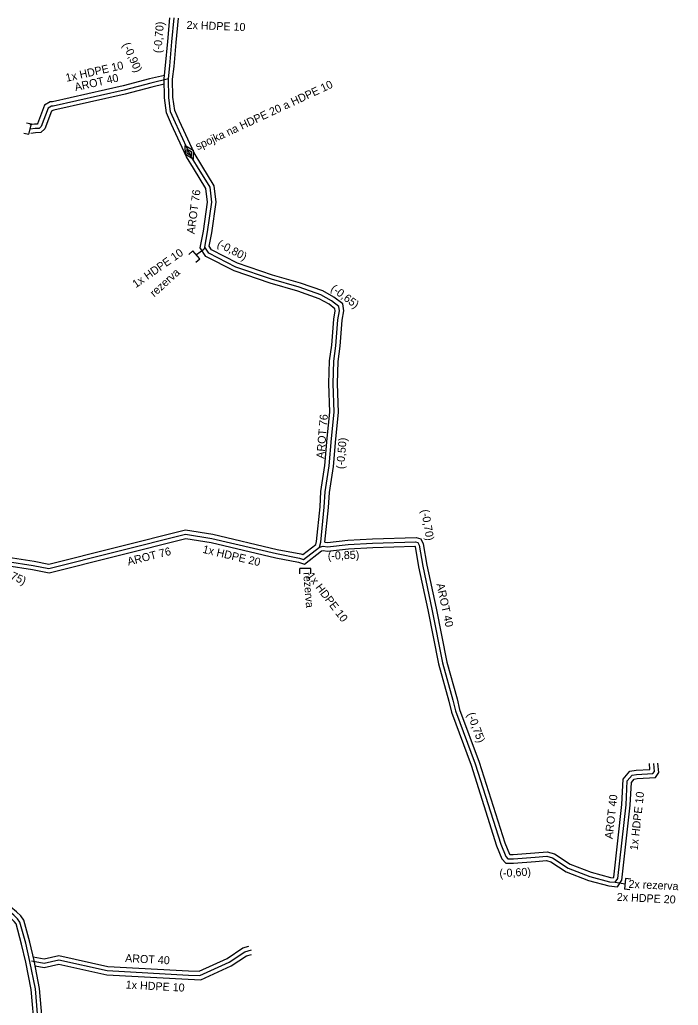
# Model space of a CAD drawing. Extents: x -651943 to -618711, y -1138561 to -1100552.
# Drawn here: x -634858.3 to -634796.6, y -1115408.5 to -1115316.1 of the extents above; entities that cross this region are included whole.
import ezdxf

# ---------------------------------------------------------------- set-up
doc = ezdxf.new("R2010")
doc.units = 0
for name, color, linetype in [('KT optika', 7, 'Continuous'), ('KT trasa', 7, 'Continuous'), ('KT zařízení', 7, 'Continuous')]:
    doc.layers.add(name, color=color, linetype=linetype)

# ---------------------------------------------------------------- blocks, each defined once
blk = doc.blocks.new('TVSPO_1')
at = {"layer": 'KT zařízení'}
for p, q in [((-0.074, 0.0016), (-0.0005, 0.0439)), ((-0.0005, -0.0409), (-0.074, 0.0016)), ((-0.0353, -0.0001), (0, 0.0203)), ((-0.0005, 0.0439), (0.0728, 0.0015)), ((0.0728, 0.0015), (-0.0005, -0.0409)), ((0, 0.0203), (0.0353, 0.0001)), ((0.0353, 0.0001), (0, -0.0204)), ((0, -0.0204), (-0.0353, -0.0001))]:
    blk.add_line(p, q, dxfattribs=at)
blk = doc.blocks.new('TVREZ')
at = {"layer": 'KT zařízení'}
for p, q in [((-0.05, 0.05), (0, 0.05)), ((0, -0.05), (0, 0.05)), ((-0.05, -0.05), (0, -0.05))]:
    blk.add_line(p, q, dxfattribs=at)

msp = doc.modelspace()

# ---------------------------------------------------------------- linework, layer by layer
at = {"layer": 'KT optika'}
for p, q in [((-634842.79, -1115364.35), (-634840.32, -1115364.75)), ((-634802.52, -1115396.99), (-634801.606, -1115397.145))]:
    msp.add_line(p, q, dxfattribs=at)
for points in [[(-634841.66, -1115329.93), (-634842.35, -1115328.79), (-634843.74, -1115325.8), (-634844.19, -1115324.75), (-634844.37, -1115323.43), (-634844.4, -1115321.67), (-634844.27, -1115320.46), (-634844.07, -1115318.21), (-634843.85, -1115315.96)], [(-634844.4, -1115321.67), (-634846.06, -1115322.06), (-634848.54, -1115322.72), (-634855.19, -1115324.22), (-634855.36, -1115324.23), (-634855.68, -1115324.42), (-634856.32, -1115326.13), (-634856.52, -1115326.31), (-634856.9, -1115326.32), (-634857.342, -1115326.385)], [(-634840.34, -1115333.24), (-634840.5, -1115331.83), (-634841.66, -1115329.93)], [(-634830.24, -1115365.56), (-634830.13, -1115365.11), (-634829.79, -1115361.83), (-634829.71, -1115360.39), (-634829.33, -1115357.96), (-634829.11, -1115355.38), (-634828.87, -1115352.93), (-634828.95, -1115350.24), (-634828.89, -1115348.14), (-634828.7, -1115346.69), (-634828.51, -1115344.25), (-634828.354, -1115343.417), (-634828.422, -1115342.998), (-634829.126, -1115342.471), (-634830.101, -1115341.917), (-634832.145, -1115341.2), (-634834.75, -1115340.445), (-634838.094, -1115339.309), (-634840.626, -1115338.011), (-634840.992, -1115337.444), (-634840.721, -1115336.024), (-634840.34, -1115333.24)], [(-634840.992, -1115337.444), (-634841.08, -1115337.67), (-634841.78, -1115338.16)], [(-634857.06, -1115367.28), (-634855.6, -1115367.56), (-634842.79, -1115364.35), (-634840.32, -1115364.75), (-634834.27, -1115366.18)], [(-634866.13, -1115365.07), (-634864.21, -1115365.83), (-634862.51, -1115366.54), (-634861.65, -1115366.57), (-634859.49, -1115366.91), (-634857.06, -1115367.28)], [(-634834.27, -1115366.18), (-634832.1, -1115366.6), (-634831.73, -1115366.72), (-634830.24, -1115365.56), (-634829.91, -1115365.47), (-634829.49, -1115365.54), (-634827.55, -1115365.33), (-634825.26, -1115365.19), (-634821.24, -1115365.06), (-634821.03, -1115365.13), (-634820.9, -1115365.39), (-634820.57, -1115367.34), (-634819.7, -1115371.37), (-634818.71, -1115376.43), (-634817.74, -1115379.9), (-634817.49, -1115380.92), (-634815.64, -1115385.87), (-634813.26, -1115393.42), (-634812.79, -1115394.57), (-634812.6, -1115394.8), (-634812.07, -1115394.79), (-634810.02, -1115394.63), (-634808.939, -1115394.544), (-634808.397, -1115394.688), (-634806.94, -1115395.66), (-634804.91, -1115396.43), (-634803.05, -1115396.94), (-634802.52, -1115396.99), (-634802.28, -1115396.64), (-634801.51, -1115389.74), (-634801.4, -1115387.48), (-634800.95, -1115386.95), (-634800.52, -1115386.87), (-634798.99, -1115386.79), (-634798.86, -1115386.59), (-634798.917, -1115385.837)], [(-634857.756, -1115443.558), (-634856.196, -1115437.459), (-634855.073, -1115432.467), (-634854.315, -1115428.401), (-634854.12, -1115426.649), (-634854.295, -1115424.564), (-634854.363, -1115424.131), (-634854.471, -1115423.78), (-634854.74, -1115423.07), (-634855.771, -1115420.67), (-634856.123, -1115416.425), (-634856.529, -1115410.896), (-634856.867, -1115406.99), (-634857.381, -1115404.408), (-634857.768, -1115402.684), (-634858.309, -1115400.724), (-634858.539, -1115400.4), (-634858.891, -1115400.062), (-634859.92, -1115399.223), (-634862.06, -1115398.101), (-634864.36, -1115396.34), (-634866.769, -1115395.591)], [(-634857.24, -1115404.36), (-634856.04, -1115404.56), (-634854.68, -1115404.25), (-634850.13, -1115405.27), (-634842.53, -1115405.68), (-634841.45, -1115405.74), (-634838.7, -1115404.48), (-634837.25, -1115403.51), (-634836.609, -1115403.321)]]:
    msp.add_lwpolyline(points, dxfattribs=at)
at = {"layer": 'KT trasa'}
for p, q in [((-634842.79, -1115364.35), (-634840.32, -1115364.75)), ((-634802.52, -1115396.99), (-634801.606, -1115397.145))]:
    msp.add_line(p, q, dxfattribs=at)
for points in [[(-634841.66, -1115329.93), (-634842.35, -1115328.79), (-634843.74, -1115325.8), (-634844.19, -1115324.75), (-634844.37, -1115323.43), (-634844.4, -1115321.67), (-634844.27, -1115320.46), (-634844.07, -1115318.21), (-634843.85, -1115315.96)], [(-634844.4, -1115321.67), (-634846.06, -1115322.06), (-634848.54, -1115322.72), (-634855.19, -1115324.22), (-634855.36, -1115324.23), (-634855.68, -1115324.42), (-634856.32, -1115326.13), (-634856.52, -1115326.31), (-634856.9, -1115326.32), (-634857.342, -1115326.385)], [(-634840.34, -1115333.24), (-634840.5, -1115331.83), (-634841.66, -1115329.93)], [(-634830.24, -1115365.56), (-634830.13, -1115365.11), (-634829.79, -1115361.83), (-634829.71, -1115360.39), (-634829.33, -1115357.96), (-634829.11, -1115355.38), (-634828.87, -1115352.93), (-634828.95, -1115350.24), (-634828.89, -1115348.14), (-634828.7, -1115346.69), (-634828.51, -1115344.25), (-634828.354, -1115343.417), (-634828.422, -1115342.998), (-634829.126, -1115342.471), (-634830.101, -1115341.917), (-634832.145, -1115341.2), (-634834.75, -1115340.445), (-634838.094, -1115339.309), (-634840.626, -1115338.011), (-634840.992, -1115337.444), (-634840.721, -1115336.024), (-634840.34, -1115333.24)], [(-634840.992, -1115337.444), (-634841.08, -1115337.67), (-634841.78, -1115338.16)], [(-634857.06, -1115367.28), (-634855.6, -1115367.56), (-634842.79, -1115364.35), (-634840.32, -1115364.75), (-634834.27, -1115366.18)], [(-634866.13, -1115365.07), (-634864.21, -1115365.83), (-634862.51, -1115366.54), (-634861.65, -1115366.57), (-634859.49, -1115366.91), (-634857.06, -1115367.28)], [(-634834.27, -1115366.18), (-634832.1, -1115366.6), (-634831.73, -1115366.72), (-634830.24, -1115365.56), (-634829.91, -1115365.47), (-634829.49, -1115365.54), (-634827.55, -1115365.33), (-634825.26, -1115365.19), (-634821.24, -1115365.06), (-634821.03, -1115365.13), (-634820.9, -1115365.39), (-634820.57, -1115367.34), (-634819.7, -1115371.37), (-634818.71, -1115376.43), (-634817.74, -1115379.9), (-634817.49, -1115380.92), (-634815.64, -1115385.87), (-634813.26, -1115393.42), (-634812.79, -1115394.57), (-634812.6, -1115394.8), (-634812.07, -1115394.79), (-634810.02, -1115394.63), (-634808.939, -1115394.544), (-634808.397, -1115394.688), (-634806.94, -1115395.66), (-634804.91, -1115396.43), (-634803.05, -1115396.94), (-634802.52, -1115396.99), (-634802.28, -1115396.64), (-634801.51, -1115389.74), (-634801.4, -1115387.48), (-634800.95, -1115386.95), (-634800.52, -1115386.87), (-634798.99, -1115386.79), (-634798.86, -1115386.59), (-634798.917, -1115385.837)], [(-634857.756, -1115443.558), (-634856.196, -1115437.459), (-634855.073, -1115432.467), (-634854.315, -1115428.401), (-634854.12, -1115426.649), (-634854.295, -1115424.564), (-634854.363, -1115424.131), (-634854.471, -1115423.78), (-634854.74, -1115423.07), (-634855.771, -1115420.67), (-634856.123, -1115416.425), (-634856.529, -1115410.896), (-634856.867, -1115406.99), (-634857.381, -1115404.408), (-634857.768, -1115402.684), (-634858.309, -1115400.724), (-634858.539, -1115400.4), (-634858.891, -1115400.062), (-634859.92, -1115399.223), (-634862.06, -1115398.101), (-634864.36, -1115396.34), (-634866.769, -1115395.591)], [(-634857.24, -1115404.36), (-634856.04, -1115404.56), (-634854.68, -1115404.25), (-634850.13, -1115405.27), (-634842.53, -1115405.68), (-634841.45, -1115405.74), (-634838.7, -1115404.48), (-634837.25, -1115403.51), (-634836.609, -1115403.321)]]:
    msp.add_lwpolyline(points, dxfattribs=at)
at = {"layer": 'KT zařízení'}
for points in [[(-634842.052, -1115330.054), (-634842.704, -1115328.978), (-634844.105, -1115325.963), (-634844.579, -1115324.858), (-634844.77, -1115323.461), (-634844.8, -1115321.652), (-634844.668, -1115320.421), (-634844.468, -1115318.173), (-634844.25, -1115315.936)], [(-634841.278, -1115329.79), (-634841.996, -1115328.602), (-634843.375, -1115325.637), (-634843.801, -1115324.642), (-634843.97, -1115323.399), (-634844, -1115321.688), (-634843.872, -1115320.499), (-634843.672, -1115318.247), (-634843.45, -1115315.984)], [(-634844.767, -1115321.346), (-634846.157, -1115321.672), (-634848.635, -1115322.331), (-634855.246, -1115323.823), (-634855.481, -1115323.836), (-634856.005, -1115324.148), (-634856.66, -1115325.898), (-634856.678, -1115325.914), (-634856.934, -1115325.921), (-634857.4, -1115325.989)], [(-634844.791, -1115322.172), (-634845.963, -1115322.448), (-634848.445, -1115323.109), (-634855.134, -1115324.617), (-634855.239, -1115324.624), (-634855.355, -1115324.692), (-634855.98, -1115326.362), (-634856.362, -1115326.706), (-634856.866, -1115326.719), (-634857.284, -1115326.781)], [(-634840.743, -1115333.235), (-634840.887, -1115331.963), (-634842.052, -1115330.054)], [(-634839.937, -1115333.245), (-634840.113, -1115331.697), (-634841.278, -1115329.79)], [(-634830.596, -1115365.33), (-634830.525, -1115365.042), (-634830.189, -1115361.798), (-634830.108, -1115360.348), (-634829.727, -1115357.912), (-634829.508, -1115355.344), (-634829.271, -1115352.916), (-634829.35, -1115350.24), (-634829.289, -1115348.108), (-634829.098, -1115346.648), (-634828.907, -1115344.198), (-634828.76, -1115343.412), (-634828.791, -1115343.221), (-634829.346, -1115342.806), (-634830.267, -1115342.283), (-634832.267, -1115341.581), (-634834.87, -1115340.827), (-634838.25, -1115339.678), (-634840.904, -1115338.318), (-634841.415, -1115337.526), (-634841.116, -1115335.959), (-634840.743, -1115333.235)], [(-634829.726, -1115365.095), (-634829.391, -1115361.862), (-634829.312, -1115360.432), (-634828.933, -1115358.008), (-634828.712, -1115355.416), (-634828.469, -1115352.944), (-634828.55, -1115350.24), (-634828.491, -1115348.172), (-634828.302, -1115346.732), (-634828.113, -1115344.302), (-634827.948, -1115343.422), (-634828.053, -1115342.775), (-634828.906, -1115342.136), (-634829.935, -1115341.551), (-634832.023, -1115340.819), (-634834.63, -1115340.063), (-634837.938, -1115338.94), (-634840.348, -1115337.704), (-634840.569, -1115337.362), (-634840.326, -1115336.089), (-634839.937, -1115333.245)], [(-634856.978, -1115366.888), (-634855.611, -1115367.151), (-634842.807, -1115363.942), (-634840.242, -1115364.357), (-634834.199, -1115365.786)], [(-634865.996, -1115364.693), (-634864.059, -1115365.459), (-634862.423, -1115366.143), (-634861.612, -1115366.171), (-634859.429, -1115366.515), (-634856.978, -1115366.888)], [(-634857.142, -1115367.672), (-634855.589, -1115367.969), (-634842.773, -1115364.758), (-634840.398, -1115365.143), (-634834.341, -1115366.574)], [(-634834.199, -1115365.786), (-634832, -1115366.212), (-634831.808, -1115366.274), (-634830.596, -1115365.33)], [(-634829.726, -1115365.095), (-634829.478, -1115365.136), (-634827.584, -1115364.931), (-634825.279, -1115364.79), (-634821.181, -1115364.658), (-634820.746, -1115364.803), (-634820.516, -1115365.264), (-634820.177, -1115367.264), (-634819.308, -1115371.289), (-634818.32, -1115376.338), (-634817.353, -1115379.799), (-634817.107, -1115380.802), (-634815.262, -1115385.74), (-634812.883, -1115393.284), (-634812.443, -1115394.362), (-634812.415, -1115394.396), (-634812.089, -1115394.39), (-634810.051, -1115394.231), (-634808.902, -1115394.14), (-634808.23, -1115394.318), (-634806.756, -1115395.302), (-634804.786, -1115396.049), (-634802.978, -1115396.545), (-634802.717, -1115396.57), (-634802.666, -1115396.496), (-634801.909, -1115389.708), (-634801.793, -1115387.325), (-634801.163, -1115386.583), (-634800.567, -1115386.472), (-634799.275, -1115386.404), (-634799.316, -1115385.867)], [(-634866.264, -1115365.447), (-634864.361, -1115366.201), (-634862.597, -1115366.937), (-634861.688, -1115366.969), (-634859.551, -1115367.305), (-634857.142, -1115367.672)], [(-634834.341, -1115366.574), (-634832.2, -1115366.988), (-634831.652, -1115367.166), (-634830.057, -1115365.925), (-634829.889, -1115365.879), (-634829.502, -1115365.944), (-634827.516, -1115365.729), (-634825.241, -1115365.59), (-634821.311, -1115365.463), (-634821.284, -1115365.516), (-634820.963, -1115367.416), (-634820.092, -1115371.451), (-634819.1, -1115376.522), (-634818.127, -1115380.001), (-634817.873, -1115381.038), (-634816.018, -1115386), (-634813.637, -1115393.556), (-634813.137, -1115394.778), (-634812.785, -1115395.204), (-634812.051, -1115395.19), (-634809.989, -1115395.029), (-634808.976, -1115394.948), (-634808.564, -1115395.058), (-634807.124, -1115396.018), (-634805.034, -1115396.811), (-634803.122, -1115397.335), (-634802.323, -1115397.41), (-634801.894, -1115396.784), (-634801.111, -1115389.772), (-634801.007, -1115387.635), (-634800.737, -1115387.317), (-634800.473, -1115387.268), (-634798.766, -1115387.179), (-634798.451, -1115386.695), (-634798.518, -1115385.807)], [(-634857.366, -1115443.648), (-634855.807, -1115437.552), (-634854.681, -1115432.548), (-634853.919, -1115428.46), (-634853.718, -1115426.654), (-634853.898, -1115424.516), (-634853.972, -1115424.041), (-634854.092, -1115423.65), (-634854.369, -1115422.92), (-634855.378, -1115420.572), (-634855.724, -1115416.394), (-634856.13, -1115410.864), (-634856.47, -1115406.934), (-634856.99, -1115404.325), (-634857.38, -1115402.587), (-634857.942, -1115400.55), (-634858.235, -1115400.138), (-634858.626, -1115399.762), (-634859.699, -1115398.887), (-634861.844, -1115397.763), (-634864.173, -1115395.979), (-634866.651, -1115395.209)], [(-634858.146, -1115443.468), (-634856.585, -1115437.366), (-634855.465, -1115432.386), (-634854.711, -1115428.342), (-634854.522, -1115426.644), (-634854.692, -1115424.612), (-634854.754, -1115424.221), (-634854.85, -1115423.91), (-634855.111, -1115423.22), (-634856.164, -1115420.768), (-634856.522, -1115416.456), (-634856.928, -1115410.928), (-634857.264, -1115407.046), (-634857.772, -1115404.491), (-634858.156, -1115402.781), (-634858.676, -1115400.898), (-634858.843, -1115400.662), (-634859.156, -1115400.362), (-634860.141, -1115399.559), (-634862.276, -1115398.439), (-634864.547, -1115396.701), (-634866.887, -1115395.973)], [(-634857.067, -1115403.983), (-634856.052, -1115404.152), (-634854.681, -1115403.84), (-634850.075, -1115404.872), (-634842.508, -1115405.281), (-634841.527, -1115405.335), (-634838.896, -1115404.13), (-634837.422, -1115403.144), (-634836.853, -1115402.976)], [(-634856.89, -1115404.824), (-634856.028, -1115404.968), (-634854.679, -1115404.66), (-634850.185, -1115405.668), (-634842.552, -1115406.079), (-634841.373, -1115406.145), (-634838.504, -1115404.83), (-634837.078, -1115403.876), (-634836.627, -1115403.744)]]:
    msp.add_lwpolyline(points, dxfattribs=at)

# ---------------------------------------------------------------- block references
for name, p, xscale, yscale, rotation in [('TVREZ', (-634857.342, -1115326.385), 9.999992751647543, 9.999992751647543, -14.229661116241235), ('TVSPO_1', (-634842.452, -1115328.57), 9.999977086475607, 9.99997708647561, -59.16953296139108), ('TVREZ', (-634841.78, -1115338.16), 10.000001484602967, 10.000001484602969, 42.27038671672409), ('TVREZ', (-634831.567, -1115367.571), 10, 10, 90), ('TVREZ', (-634801.606, -1115397.145), 9.999988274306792, 9.99998827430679, 175.13162233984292)]:
    msp.add_blockref(name, p, dxfattribs=dict(at, xscale=xscale, yscale=yscale, rotation=rotation))

# ---------------------------------------------------------------- texts
for s, rotation, p in [('(-0,70)', 84.9159, (-634845.068, -1115319.279)), ('2x HDPE 10', 357.81723, (-634842.708, -1115316.979)), ('(-0,90)', 294.30643, (-634848.715, -1115318.453)), ('1x HDPE 10', 12.71771, (-634853.943, -1115321.95)), ('AROT 40', 12.71771, (-634853.095, -1115322.825)), ('spojka na HDPE 20 a HDPE 10', 24.93291, (-634841.654, -1115328.373)), ('AROT 76', 82.20292, (-634841.951, -1115336.249)), ('1x HDPE 10', 34.99202, (-634847.452, -1115341.304)), ('(-0,80)', 332.84839, (-634839.903, -1115337.37)), ('rezerva', 42.24284, (-634845.728, -1115342.16)), ('(-0,65)', 323.16236, (-634829.251, -1115341.466)), ('AROT 76', 85.12559, (-634829.801, -1115357.303)), ('(-0,50)', 85.12661, (-634827.94, -1115358.275)), ('(-0,70)', 279.6202, (-634820.717, -1115362.098)), ('AROT 76', 14.06569, (-634848.149, -1115367.296)), ('1x HDPE 20', 346.70729, (-634841.245, -1115366.092)), ('(-0,85)', 2.15391, (-634829.451, -1115366.752)), ('(-0,75)', 334.83739, (-634860.622, -1115367.875)), ('rezerva', 274.89756, (-634831.773, -1115367.949)), ('1x HDPE 10', 307.28005, (-634831.462, -1115368.283)), ('AROT 40', 282.18319, (-634819.283, -1115369.035)), ('(-0,75)', 290.48735, (-634816.418, -1115381.218)), ('AROT 40', 83.63665, (-634802.774, -1115392.956)), ('1x HDPE 10', 83.62842, (-634800.427, -1115394.023)), ('(-0,60)', 3.14559, (-634813.359, -1115396.518)), ('2x rezerva', 357.27369, (-634801.296, -1115397.509)), ('2x HDPE 20', 357.27369, (-634802.393, -1115398.723)), ('AROT 40', 356.90615, (-634848.468, -1115404.458)), ('1x HDPE 10', 356.90615, (-634848.412, -1115406.946))]:
    msp.add_text(s, height=0.75, rotation=rotation, dxfattribs=at).set_placement(p)

doc.saveas('drawing.dxf')
